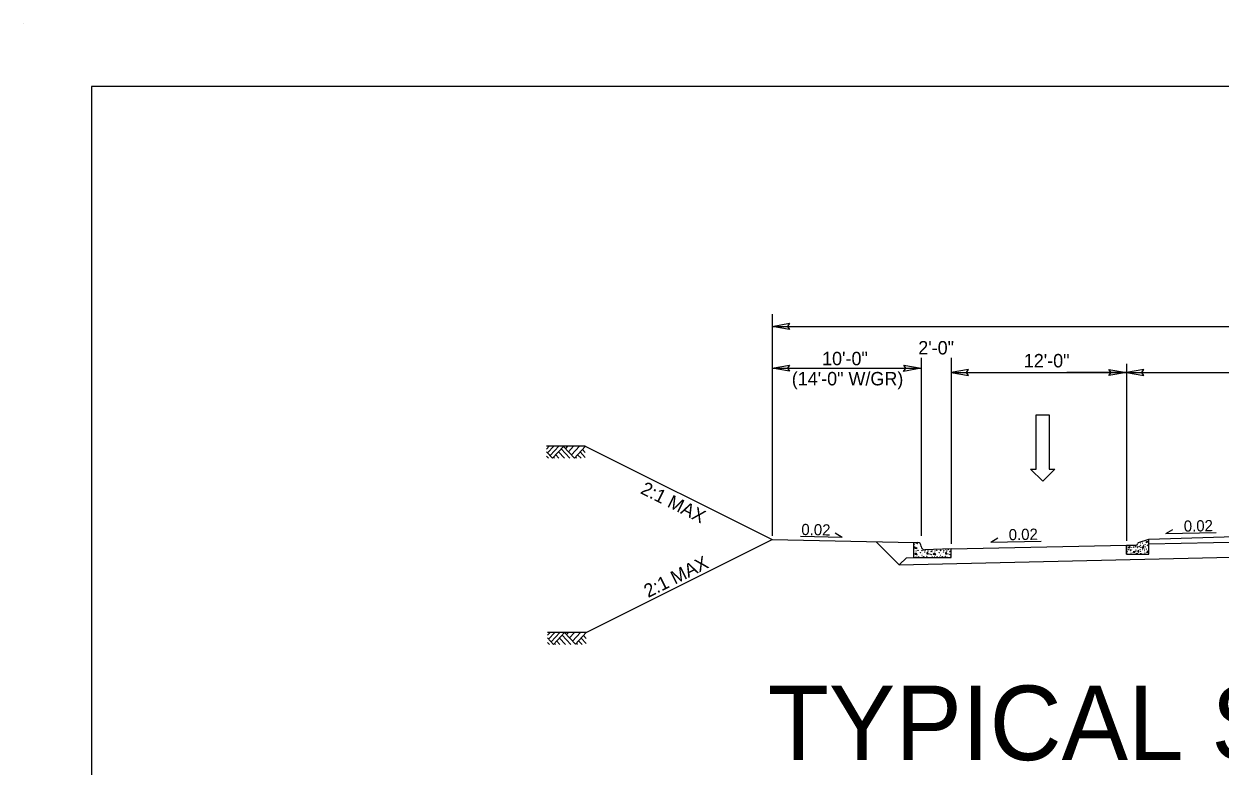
# Model space of a CAD drawing. Extents: x 1904401 to 1905163, y 193929 to 194736.
# Drawn here: x 1904498 to 1904578.2, y 194476.7 to 194526.5 of the extents above; entities that cross this region are included whole.
import ezdxf

# ---------------------------------------------------------------- set-up
doc = ezdxf.new("R2010")
doc.units = 0
for name, color, linetype in [('Default', 7, 'Continuous'), ('Old_Level_1', 7, 'Continuous'), ('Old_Level_2', 7, 'Continuous'), ('Prop Dimension Text', 7, 'Continuous'), ('Prop Lane Arrow CELL', 7, 'Continuous'), ('Scratch_Level_3', 7, 'Continuous'), ('Typical Arrow Superelevation CELL', 7, 'Continuous'), ('Typical Berm CELL', 7, 'Continuous'), ('Typical Curb CELL', 7, 'Continuous'), ('Typical Hinge Slope Arterial CELL', 7, 'Continuous'), ('Typical Pavement Slope CELL', 7, 'Continuous'), ('Typical Terminator CELL', 7, 'Continuous')]:
    doc.layers.add(name, color=color, linetype=linetype)

msp = doc.modelspace()

# ---------------------------------------------------------------- linework, layer by layer
at = {"layer": 'Default'}
for p, q in [((1904560.132, 194504.057), (1904560.132, 194491.759)), ((1904560.132, 194503.712), (1904560.132, 194491.67)), ((1904571.882, 194503.712), (1904571.882, 194491.84))]:
    msp.add_line(p, q, dxfattribs=at)
at = {"layer": 'Old_Level_1'}
for p, q in [((1904548.132, 194506.221), (1904611.632, 194506.221)), ((1904571.882, 194503.129), (1904587.882, 194503.129)), ((1904533.182, 194498.177), (1904533.012, 194497.994)), ((1904533.502, 194498.177), (1904533.088, 194497.733)), ((1904533.835, 194498.177), (1904533.255, 194497.554)), ((1904534.157, 194498.176), (1904533.416, 194497.38)), ((1904534.578, 194497.372), (1904533.992, 194498)), ((1904534.888, 194497.39), (1904534.157, 194498.176)), ((1904534.421, 194498.177), (1904534.288, 194498.034)), ((1904534.823, 194498.177), (1904534.49, 194497.818)), ((1904535.221, 194498.177), (1904534.688, 194497.604)), ((1904535.612, 194498.169), (1904534.888, 194497.39)), ((1904535.612, 194497.768), (1904535.426, 194497.968)), ((1904533.416, 194497.38), (1904533.012, 194497.815)), ((1904533.146, 194497.372), (1904533.012, 194497.515)), ((1904533.547, 194497.372), (1904533.478, 194497.446)), ((1904533.842, 194497.372), (1904533.625, 194497.605)), ((1904534.208, 194497.372), (1904533.808, 194497.801)), ((1904535.013, 194497.372), (1904534.942, 194497.448)), ((1904535.324, 194497.372), (1904535.097, 194497.615)), ((1904535.612, 194497.435), (1904535.27, 194497.801)), ((1904533.249, 194485.691), (1904533.079, 194485.508)), ((1904533.483, 194484.894), (1904533.079, 194485.329)), ((1904533.569, 194485.691), (1904533.155, 194485.247)), ((1904533.902, 194485.691), (1904533.322, 194485.068)), ((1904534.224, 194485.69), (1904533.483, 194484.894)), ((1904534.275, 194484.886), (1904533.875, 194485.315)), ((1904534.645, 194484.886), (1904534.059, 194485.514)), ((1904534.955, 194484.904), (1904534.224, 194485.69)), ((1904534.488, 194485.691), (1904534.355, 194485.548)), ((1904534.89, 194485.691), (1904534.557, 194485.332)), ((1904535.288, 194485.691), (1904534.755, 194485.118)), ((1904535.679, 194485.683), (1904534.955, 194484.904)), ((1904535.679, 194484.949), (1904535.337, 194485.315)), ((1904535.679, 194485.282), (1904535.493, 194485.482)), ((1904533.213, 194484.886), (1904533.079, 194485.029)), ((1904533.614, 194484.886), (1904533.545, 194484.96)), ((1904533.909, 194484.886), (1904533.692, 194485.119)), ((1904535.08, 194484.886), (1904535.009, 194484.962)), ((1904535.391, 194484.886), (1904535.164, 194485.129))]:
    msp.add_line(p, q, dxfattribs=at)
for points in [[(1904535.612, 194498.177), (1904533.012, 194498.177)], [(1904535.679, 194485.691), (1904533.079, 194485.691)]]:
    msp.add_lwpolyline(points, dxfattribs=at)
at = {"layer": 'Old_Level_2'}
msp.add_lwpolyline([(1904502.509, 194403.25), (1904658.329, 194403.25), (1904658.329, 194522.32), (1904502.509, 194522.32)], close=True, dxfattribs=at)
at = {"layer": 'Prop Dimension Text'}
for p, q in [((1904548.132, 194507.049), (1904548.132, 194492.183)), ((1904558.132, 194504.102), (1904558.132, 194492.183)), ((1904560.132, 194504.102), (1904560.132, 194491.645)), ((1904548.132, 194503.409), (1904558.132, 194503.409)), ((1904560.132, 194503.129), (1904572.132, 194503.129)), ((1904560.882, 194503.129), (1904571.882, 194503.129)), ((1904571.882, 194503.129), (1904567.882, 194503.129))]:
    msp.add_line(p, q, dxfattribs=at)
at = {"layer": 'Prop Lane Arrow CELL'}
for p, q in [((1904565.845, 194500.28), (1904566.701, 194500.28)), ((1904565.845, 194496.649), (1904565.845, 194500.28)), ((1904566.701, 194500.28), (1904566.701, 194496.649)), ((1904566.286, 194495.831), (1904565.456, 194496.649)), ((1904565.456, 194496.649), (1904565.845, 194496.649)), ((1904567.09, 194496.649), (1904566.286, 194495.831)), ((1904566.701, 194496.649), (1904567.09, 194496.649))]:
    msp.add_line(p, q, dxfattribs=at)
at = {"layer": 'Scratch_Level_3'}
msp.add_line((1904497.977, 194526.509), (1904497.977, 194526.509), dxfattribs=at)
at = {"layer": 'Typical Arrow Superelevation CELL'}
for p, q in [((1904574.53, 194492.32), (1904575, 194492.604)), ((1904574.53, 194492.32), (1904577.905, 194492.388)), ((1904552.83, 194492.062), (1904550.033, 194492.118)), ((1904552.83, 194492.062), (1904552.36, 194492.346)), ((1904562.793, 194491.746), (1904563.263, 194492.03)), ((1904562.793, 194491.746), (1904566.167, 194491.813))]:
    msp.add_line(p, q, dxfattribs=at)
at = {"layer": 'Typical Berm CELL'}
msp.add_line((1904548.132, 194491.917), (1904557.633, 194491.719), dxfattribs=at)
at = {"layer": 'Typical Curb CELL'}
for p, q in [((1904557.633, 194490.719), (1904557.633, 194491.719)), ((1904557.633, 194491.719), (1904557.893, 194491.719)), ((1904572.632, 194491.631), (1904572.632, 194491.637)), ((1904572.696, 194491.726), (1904573.382, 194491.954)), ((1904573.235, 194491.783), (1904573.321, 194491.783)), ((1904573.24, 194491.696), (1904573.235, 194491.783)), ((1904573.321, 194491.783), (1904573.24, 194491.696)), ((1904573.382, 194490.954), (1904573.382, 194491.954)), ((1904557.669, 194491.341), (1904557.823, 194491.386)), ((1904557.806, 194491.295), (1904557.669, 194491.341)), ((1904557.795, 194491.022), (1904557.692, 194490.947)), ((1904557.692, 194490.947), (1904557.857, 194490.908)), ((1904557.857, 194490.908), (1904557.795, 194491.022)), ((1904557.823, 194491.386), (1904557.806, 194491.295)), ((1904558.132, 194491.469), (1904558.132, 194491.48)), ((1904560.132, 194491.303), (1904558.382, 194491.23)), ((1904558.537, 194491.079), (1904558.502, 194490.965)), ((1904558.502, 194490.965), (1904558.622, 194490.959)), ((1904558.622, 194490.959), (1904558.537, 194491.079)), ((1904559.044, 194491.022), (1904558.941, 194490.947)), ((1904558.941, 194490.947), (1904559.106, 194490.908)), ((1904559.106, 194490.908), (1904559.044, 194491.022)), ((1904559.785, 194491.079), (1904559.751, 194490.965)), ((1904559.751, 194490.965), (1904559.872, 194490.959)), ((1904559.872, 194490.959), (1904559.785, 194491.079)), ((1904560.132, 194490.719), (1904560.132, 194491.303)), ((1904571.882, 194491.538), (1904571.882, 194490.954)), ((1904571.882, 194491.538), (1904572.538, 194491.538)), ((1904571.882, 194490.954), (1904571.882, 194491.531)), ((1904571.882, 194490.954), (1904573.382, 194490.954)), ((1904572.035, 194491.406), (1904572.118, 194491.464)), ((1904572.076, 194491.316), (1904572.035, 194491.406)), ((1904572.118, 194491.464), (1904572.076, 194491.316)), ((1904572.375, 194491.148), (1904572.447, 194491.134)), ((1904572.41, 194491.026), (1904572.375, 194491.148)), ((1904572.447, 194491.134), (1904572.41, 194491.026)), ((1904572.729, 194491.191), (1904572.639, 194491.141)), ((1904572.639, 194491.141), (1904572.697, 194491.06)), ((1904572.697, 194491.06), (1904572.729, 194491.191)), ((1904572.955, 194491.421), (1904573.037, 194491.48)), ((1904572.995, 194491.33), (1904572.955, 194491.421)), ((1904573.037, 194491.48), (1904572.995, 194491.33)), ((1904573.294, 194491.164), (1904573.366, 194491.15)), ((1904573.33, 194491.041), (1904573.294, 194491.164)), ((1904573.366, 194491.15), (1904573.33, 194491.041)), ((1904557.633, 194490.719), (1904560.132, 194490.719))]:
    msp.add_line(p, q, dxfattribs=at)
for centre, radius in [((1904557.646, 194491.609), 0.00802), ((1904557.863, 194491.643), 0.00802), ((1904572.819, 194491.701), 0.00635), ((1904572.955, 194491.679), 0.00635), ((1904573.145, 194491.584), 0.00635), ((1904573.172, 194491.868), 0.00635), ((1904557.697, 194491.426), 0.00802), ((1904557.777, 194490.765), 0.00802), ((1904557.794, 194491.153), 0.00802), ((1904557.914, 194491.204), 0.00802), ((1904557.948, 194490.805), 0.00802), ((1904558.091, 194491.039), 0.00802), ((1904558.125, 194490.742), 0.00802), ((1904558.171, 194491.232), 0.00802), ((1904558.183, 194490.857), 0.00802), ((1904558.188, 194491.182), 0.00802), ((1904558.217, 194491.011), 0.00802), ((1904558.297, 194490.771), 0.00802), ((1904558.365, 194491.096), 0.00802), ((1904558.394, 194491.198), 0.00802), ((1904558.502, 194490.794), 0.00802), ((1904558.588, 194491.159), 0.00802), ((1904558.685, 194491.213), 0.00802), ((1904558.713, 194490.959), 0.00802), ((1904558.793, 194491.119), 0.00802), ((1904558.809, 194490.914), 0.00802), ((1904558.849, 194491.153), 0.00802), ((1904558.866, 194491.056), 0.00802), ((1904558.872, 194490.748), 0.00802), ((1904559.026, 194490.765), 0.00802), ((1904559.043, 194491.153), 0.00802), ((1904559.163, 194491.204), 0.00802), ((1904559.198, 194490.805), 0.00802), ((1904559.34, 194491.039), 0.00802), ((1904559.374, 194490.742), 0.00802), ((1904559.42, 194491.232), 0.00802), ((1904559.432, 194490.857), 0.00802), ((1904559.437, 194491.182), 0.00802), ((1904559.466, 194491.011), 0.00802), ((1904559.546, 194490.771), 0.00802), ((1904559.614, 194491.096), 0.00802), ((1904559.643, 194491.198), 0.00802), ((1904559.751, 194490.794), 0.00802), ((1904559.791, 194491.261), 0.00802), ((1904559.837, 194491.159), 0.00802), ((1904559.934, 194491.244), 0.00802), ((1904559.962, 194490.959), 0.00802), ((1904560.042, 194491.119), 0.00802), ((1904560.059, 194490.914), 0.00802), ((1904560.098, 194491.153), 0.00802), ((1904560.116, 194491.056), 0.00802), ((1904560.121, 194490.748), 0.00802), ((1904571.891, 194491.247), 0.00635), ((1904571.923, 194491.112), 0.00635), ((1904571.936, 194490.99), 0.00635), ((1904571.941, 194491.387), 0.00635), ((1904572.036, 194491.243), 0.00635), ((1904572.108, 194491.518), 0.00635), ((1904572.171, 194491.18), 0.00635), ((1904572.185, 194491.274), 0.00635), ((1904572.198, 194491.008), 0.00635), ((1904572.23, 194491.405), 0.00635), ((1904572.32, 194491.261), 0.00635), ((1904572.343, 194491.049), 0.00635), ((1904572.379, 194491.419), 0.00635), ((1904572.496, 194491.424), 0.00635), ((1904572.512, 194491.453), 0.00635), ((1904572.519, 194491.22), 0.00635), ((1904572.535, 194491.141), 0.00635), ((1904572.535, 194490.987), 0.00635), ((1904572.611, 194491.001), 0.00635), ((1904572.625, 194491.376), 0.00635), ((1904572.648, 194491.475), 0.00635), ((1904572.77, 194491.448), 0.00635), ((1904572.81, 194491.263), 0.00635), ((1904572.837, 194491.539), 0.00635), ((1904572.842, 194491.128), 0.00635), ((1904572.856, 194491.006), 0.00635), ((1904572.86, 194491.403), 0.00635), ((1904572.955, 194491.259), 0.00635), ((1904573.027, 194491.534), 0.00635), ((1904573.09, 194491.195), 0.00635), ((1904573.104, 194491.29), 0.00635), ((1904573.118, 194491.024), 0.00635), ((1904573.149, 194491.421), 0.00635), ((1904573.239, 194491.277), 0.00635), ((1904573.262, 194491.064), 0.00635), ((1904573.298, 194491.435), 0.00635), ((1904573.307, 194491.543), 0.00635), ((1904558.662, 194490.725), 0.00802), ((1904559.911, 194490.725), 0.00802)]:
    msp.add_circle(centre, radius, dxfattribs=at)
for centre, radius, start, end in [((1904557.893, 194491.48), 0.24, 0, 90), ((1904572.538, 194491.631), 0.0937, 270, 0), ((1904572.726, 194491.637), 0.0937, 108.43495, 180), ((1904558.372, 194491.469), 0.24, 180, 272.38446), ((1904573.348, 194490.96), 0.00635, 25.75843, 152.96144)]:
    msp.add_arc(centre, radius, start, end, dxfattribs=at)
at = {"layer": 'Typical Hinge Slope Arterial CELL'}
for p in [(1904535.612, 194498.177), (1904535.679, 194485.691)]:
    msp.add_line(p, (1904548.132, 194491.917), dxfattribs=at)
at = {"layer": 'Typical Pavement Slope CELL'}
for p, q in [((1904556.65, 194490.226), (1904555.104, 194491.772)), ((1904573.382, 194491.954), (1904579.882, 194492.161)), ((1904573.382, 194491.638), (1904579.882, 194491.768)), ((1904556.65, 194490.226), (1904579.882, 194490.761)), ((1904560.132, 194491.303), (1904571.882, 194491.538)), ((1904556.65, 194490.226), (1904557.133, 194490.709)), ((1904557.133, 194490.709), (1904557.633, 194490.719))]:
    msp.add_line(p, q, dxfattribs=at)
at = {"layer": 'Typical Terminator CELL'}
for points in [[(1904549.304, 194506.02), (1904548.132, 194506.221), (1904549.31, 194506.43), (1904549.161, 194506.221)], [(1904549.304, 194503.207), (1904548.132, 194503.409), (1904549.31, 194503.617), (1904549.161, 194503.409)], [(1904556.96, 194503.611), (1904558.132, 194503.409), (1904556.954, 194503.201), (1904557.104, 194503.409)], [(1904561.304, 194503.331), (1904560.132, 194503.129), (1904561.31, 194502.921), (1904561.161, 194503.129)], [(1904570.71, 194503.331), (1904571.882, 194503.129), (1904570.704, 194502.921), (1904570.854, 194503.129)], [(1904573.054, 194503.331), (1904571.882, 194503.129), (1904573.06, 194502.921), (1904572.911, 194503.129)]]:
    msp.add_lwpolyline(points, close=True, dxfattribs=at)

# ---------------------------------------------------------------- texts
at = {"layer": 'Old_Level_1'}
msp.add_text('TYPICAL SECTION 1', height=5, dxfattribs=at).set_placement((1904547.852, 194477.129))
at = {"layer": 'Prop Dimension Text'}
for s, p in [('2\'-0"', (1904557.933, 194504.339)), ('10\'-0" ', (1904551.486, 194503.615)), ('12\'-0"', (1904565.007, 194503.472)), ('(14\'-0" W/GR)', (1904549.453, 194502.265))]:
    msp.add_text(s, height=0.9, dxfattribs=at).set_placement(p)
for rotation, p in [(1.1462, (1904575.741, 194492.45)), (358.8538, (1904550.088, 194492.23)), (1.1462, (1904564.004, 194491.875))]:
    msp.add_text('0.02', height=0.7499, rotation=rotation, dxfattribs=at).set_placement(p)
at = {"layer": 'Typical Hinge Slope Arterial CELL'}
for rotation, p in [(333.43495, (1904539.248, 194495.045)), (26.56505, (1904539.823, 194488.002))]:
    msp.add_text('2:1 MAX', height=0.9, rotation=rotation, dxfattribs=at).set_placement(p)

doc.saveas('drawing.dxf')
